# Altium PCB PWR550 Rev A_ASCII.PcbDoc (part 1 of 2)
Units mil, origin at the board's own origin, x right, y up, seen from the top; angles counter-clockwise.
Board outline 5200 x 2850 mil, 4 copper layers (Top Layer, INTERNAL 1, INTERNAL 2, Bottom Layer), stack 60.3 mil thick; 145 components, 78 nets, 363 pads, 156 vias.
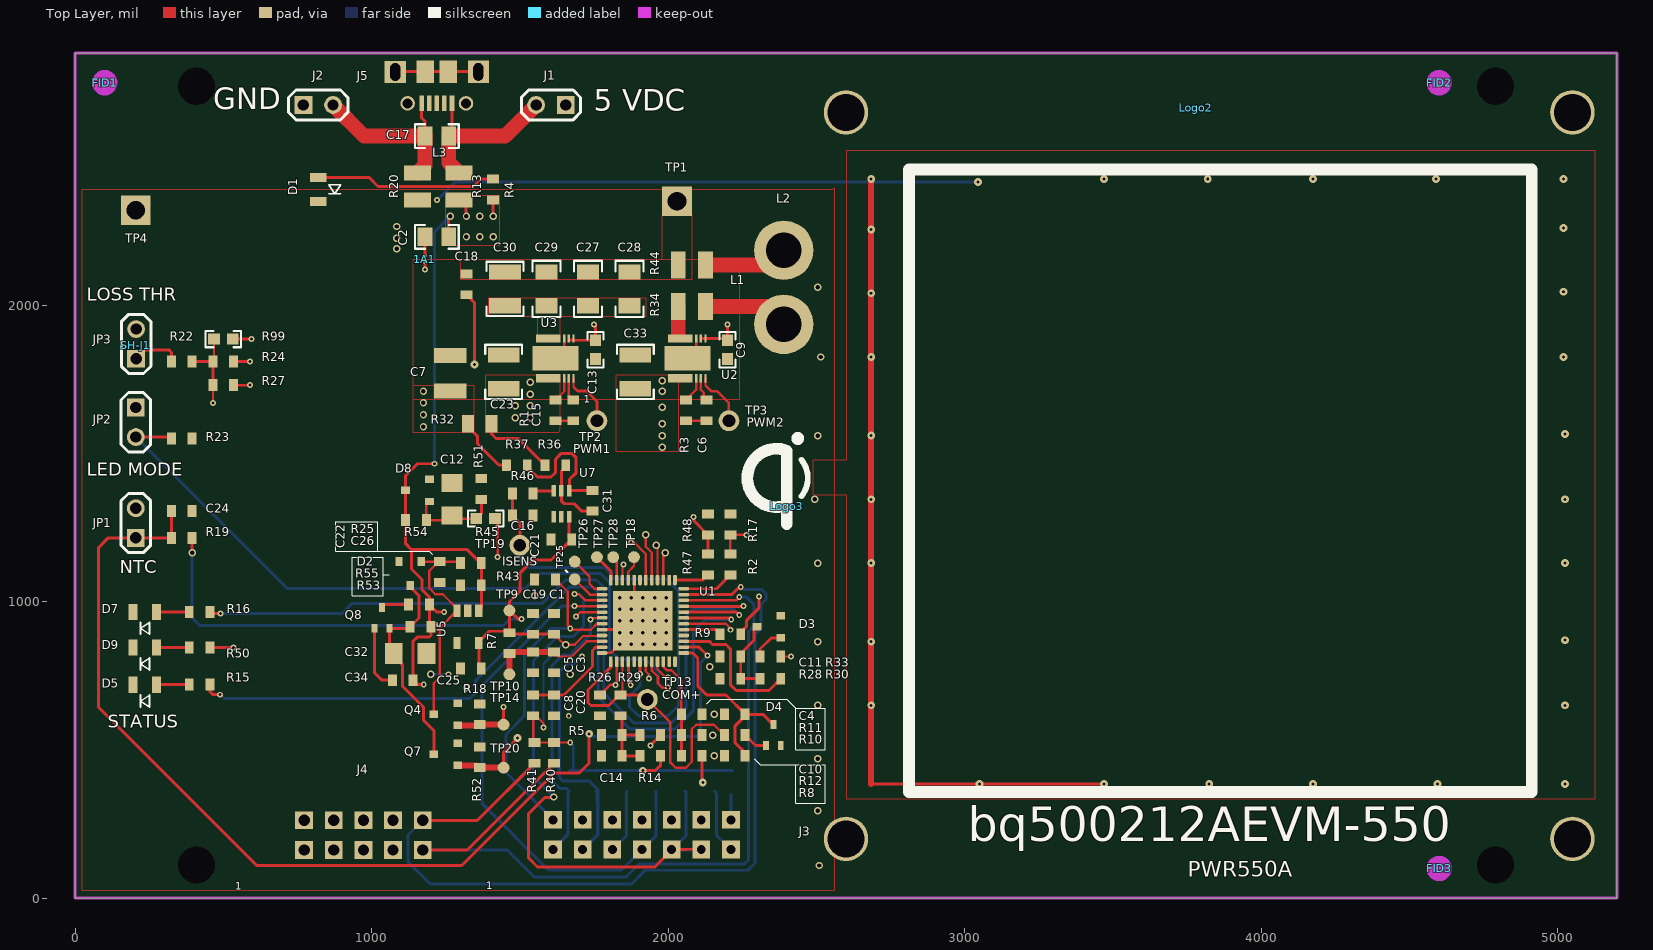
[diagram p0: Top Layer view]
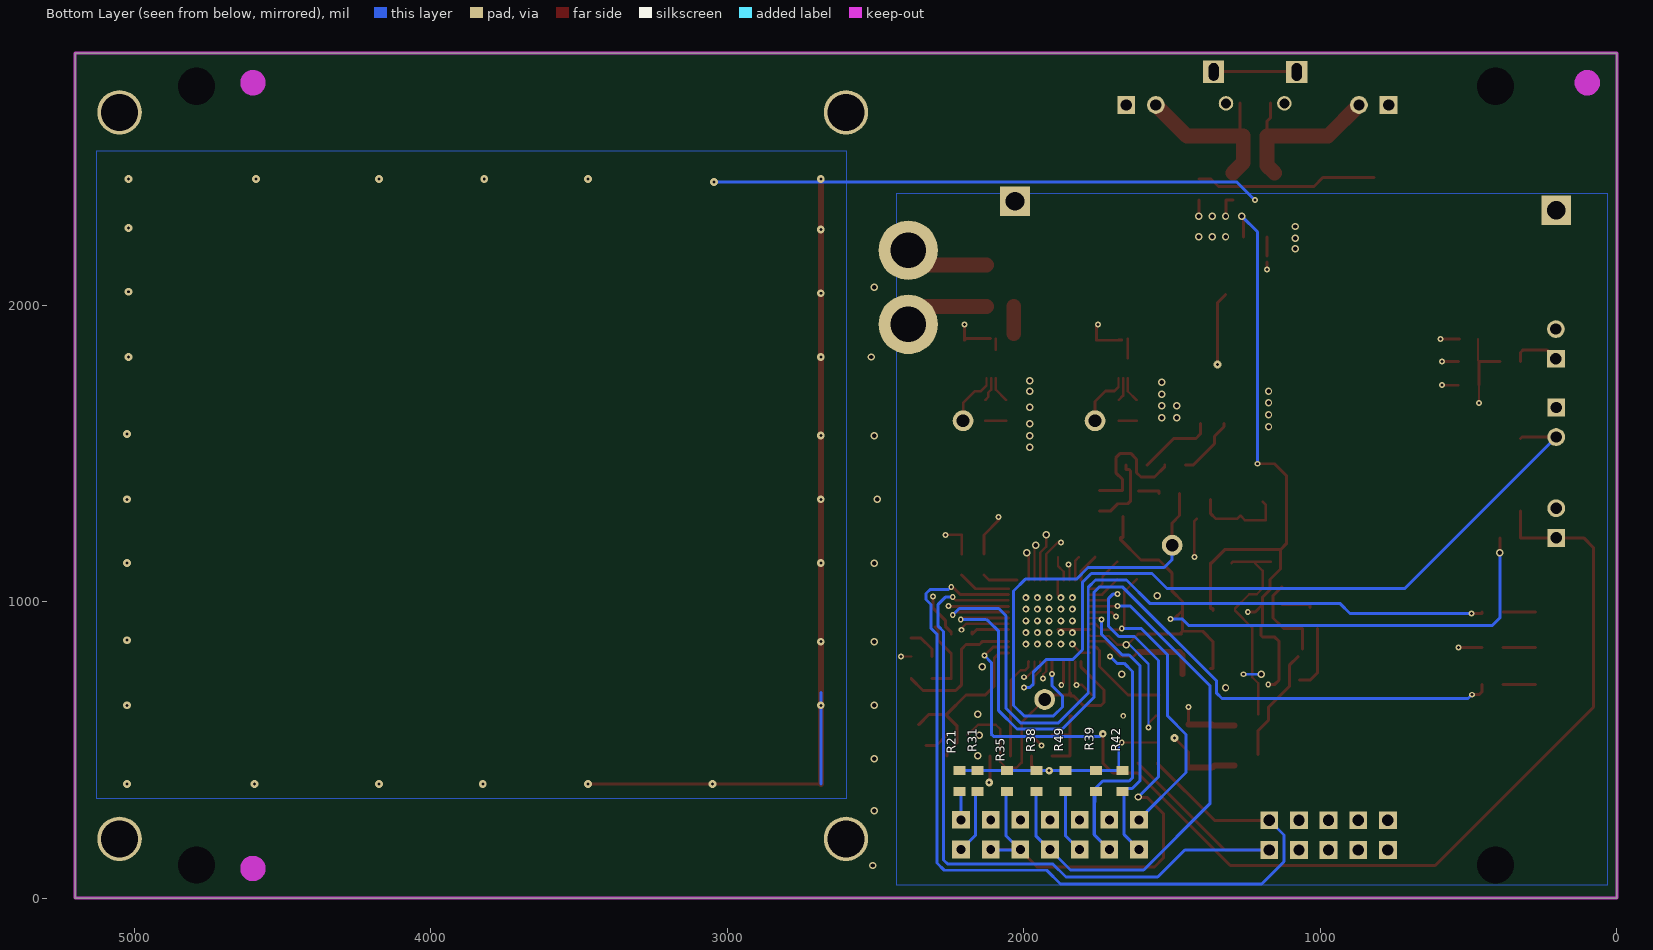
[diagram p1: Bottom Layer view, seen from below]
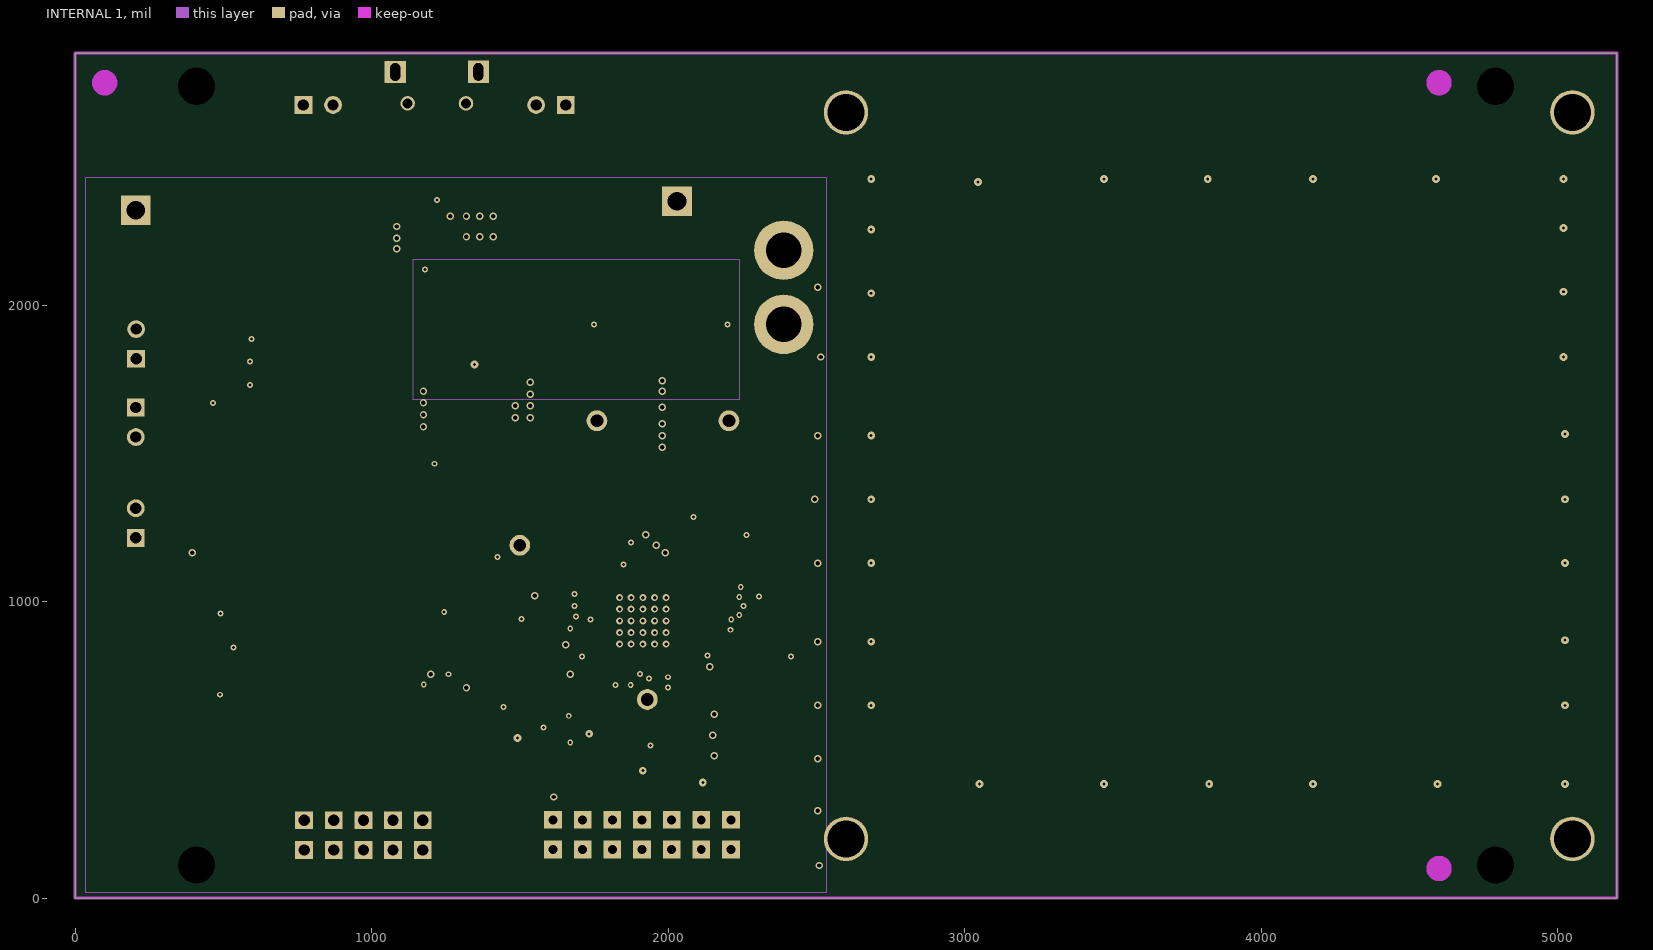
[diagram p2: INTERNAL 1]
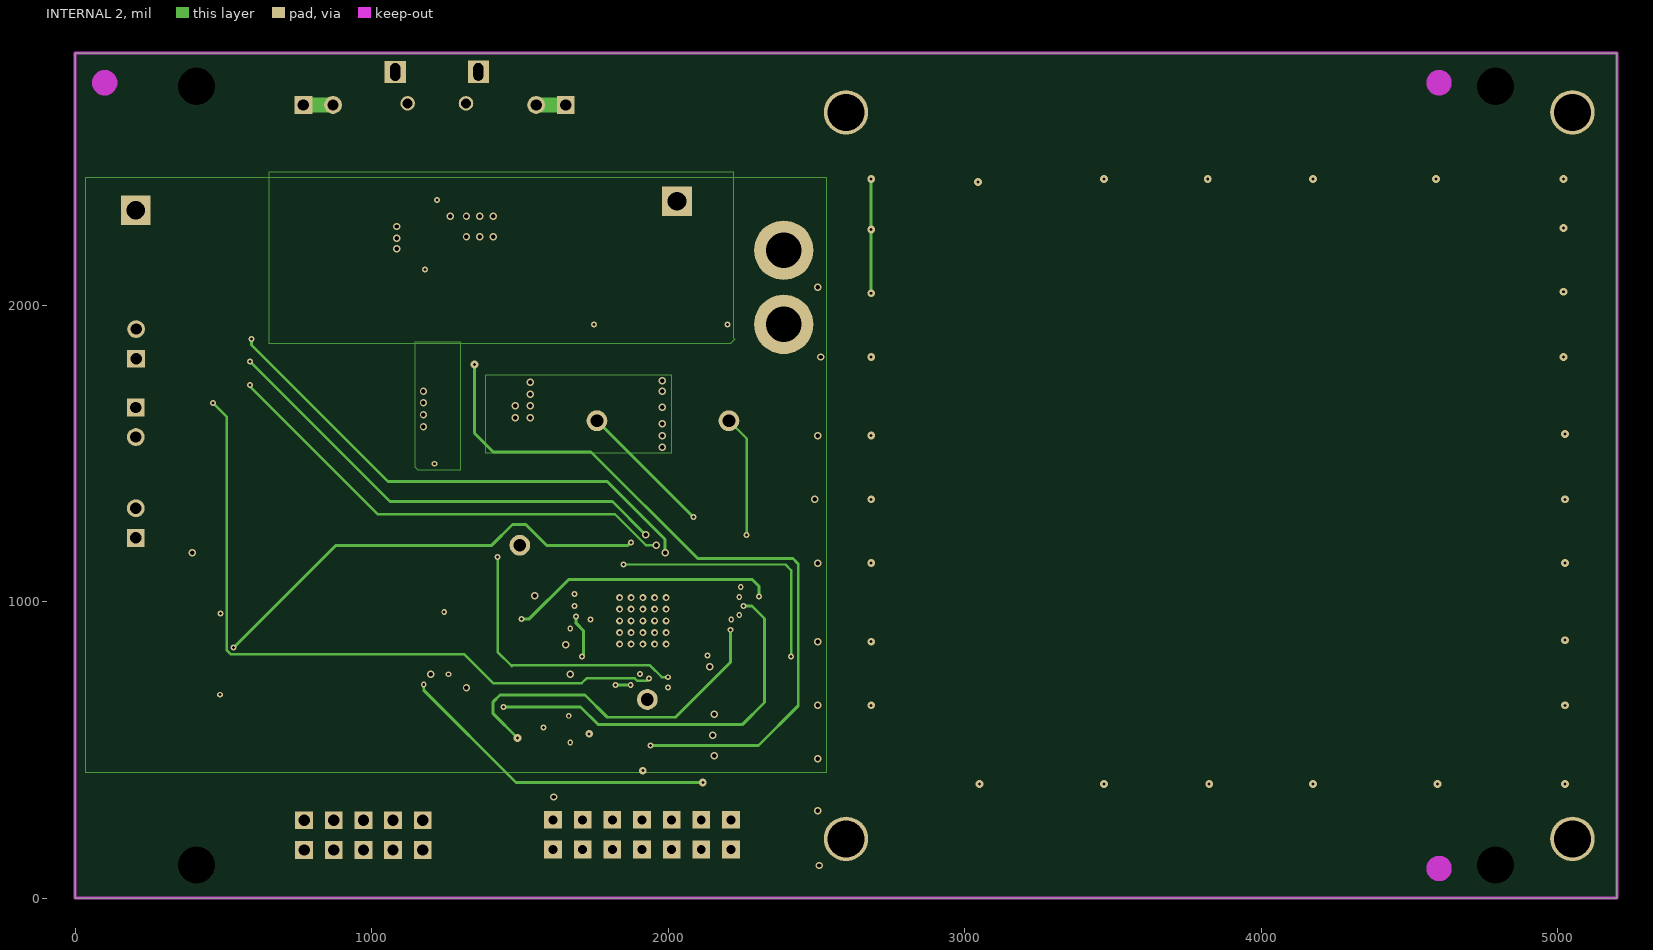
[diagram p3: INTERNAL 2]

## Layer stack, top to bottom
Top Layer: signal copper 2.8
Dielectric: core 18.3, 370HR, Dk 4.8
INTERNAL 1: signal copper 2.8
Dielectric: prepreg 12.5, 370HR, Dk 4.8
INTERNAL 2: signal copper 2.8
Dielectric: core 18.3, 370HR, Dk 4.8
Bottom Layer: signal copper 2.8

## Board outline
0,0 0,2850 5200,2850 5200,0

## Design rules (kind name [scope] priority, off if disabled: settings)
AcuteAngle [All] p0: scope1count=1 scope1_0_kind=Board scope1_0_value=Board scope2count=1 scope2_0_kind=Board scope2_0_value=Board commentlength=0 minimum=4.50000000000000E+0001
AcuteAngle [All] p1: minimum=4.50000000000000E+0001 checktracksonly=FALSE
AssemblyTestPointUsage [All] p0: scope1count=1 scope1_0_kind=Board scope1_0_value=Board scope2count=1 scope2_0_kind=Board scope2_0_value=Board commentlength=0
AssemblyTestPointUsage [All] p1: valid=2
AssemblyTestpoint [All] p0: scope1count=1 scope1_0_kind=Board scope1_0_value=Board scope2count=1 scope2_0_kind=Board scope2_0_value=Board commentlength=0
Clearance [All] p0: scope1count=1 scope1_0_kind=Board scope1_0_value=Board scope2count=1 scope2_0_kind=Board scope2_0_value=Board commentlength=0 gap=7
Clearance Clearance_Poly [All] p0 off: scope1count=1 scope1_0_kind=Board scope1_0_value=Board scope2count=1 scope2_0_kind=Board scope2_0_value=Board commentlength=48 gap=10 // Protel DXP Scope 1 Expression Was: InPolygon
Clearance Clearance_BoardEdge [All] p0 off: scope1count=1 scope1_0_kind=Board scope1_0_value=Board scope2count=1 scope2_0_kind=Board scope2_0_value=Board commentlength=48 gap=25 // Protel DXP Scope 2 Expression Was: IsKeepOut
Clearance Clearance_BoardEdge_Poly [All] p0 off: scope1count=1 scope1_0_kind=Board scope1_0_value=Board scope2count=1 scope2_0_kind=Board scope2_0_value=Board commentlength=48 gap=25 // Protel DXP Scope 2 Expression Was: IsKeepOut
Clearance Clearance_BoardEdge_MountingHoles [All] p0 off: scope1count=1 scope1_0_kind=Board scope1_0_value=Board scope2count=1 scope2_0_kind=Board scope2_0_value=Board commentlength=48 gap=50 // Protel DXP Scope 2 Expression Was: IsKeepOut
Clearance Clearance_BoardEdge_MountingHoles [OnCopper and InComponentClass('Mounting Holes') vs IsKeepOut] p1: gap=50
Clearance Clearance_BoardEdge_Poly [OnCopper and InPoly vs IsKeepOut] p2: gap=25
Clearance Clearance_BoardEdge [OnCopper and Not InComponentClass('Logo') and not InComponentClass('FiducialMark') and not InRegion(1000,500,4000,800) and Not IsKeepout vs IsKeepOut] p3: gap=25
Clearance Clearance_Poly [InPolygon] p4: gap=10
Clearance [All] p5: gap=7
ComponentClearance [All] p0 off: scope1count=1 scope1_0_kind=Board scope1_0_value=Board scope2count=1 scope2_0_kind=Board scope2_0_value=Board commentlength=0 gap=10 collisioncheckmode=3
ComponentClearance ComponentClearance_THtoTH [All] p0 off: scope1count=1 scope1_0_kind=Board scope1_0_value=Board scope2count=1 scope2_0_kind=Board scope2_0_value=Board commentlength=54 gap=100 collisioncheckmode=3 // Protel DXP Scope 2 Expression Was: IsThruComponent
ComponentClearance ComponentClearance_THtoSMT [All] p0 off: scope1count=1 scope1_0_kind=Board scope1_0_value=Board scope2count=1 scope2_0_kind=Board scope2_0_value=Board commentlength=53 gap=20 collisioncheckmode=3 // Protel DXP Scope 2 Expression Was: IsSMTComponent
ComponentClearance ComponentClearance_SmallPassives [All] p0 off: scope1count=1 scope1_0_kind=Board scope1_0_value=Board scope2count=1 scope2_0_kind=Board scope2_0_value=Board commentlength=508 gap=10 collisioncheckmode=3 // Protel DXP Scope 2 Expression Was: HasFootprint('0201*') or HasFootprint('0402*') or HasFootprint('0508') or HasFootprint('0603*') or HasFootprint('0612') or HasFootprint('0805*') or HasFootprint('0815*') or HasFootprint('0830*') or HasFootprint('1206*') or HasFootprint('1210*') or HasFootprint('1808*') or HasFootprint('1812*') or HasFootprint('1825*') or HasFootprint('2010*') or HasFootprint('2220*') or HasFootprint('2225*') or HasFootprint('2512*') or HasFootprint('2728*') or HasFootprint('3518*')
ComponentClearance ComponentClearance_MountingHoles [All] p0 off: scope1count=1 scope1_0_kind=ComponentClass scope1_0_value="Mounting Holes" scope2count=1 scope2_0_kind=Board scope2_0_value=Board commentlength=0 gap=25 collisioncheckmode=3
ComponentClearance ComponentClearance_ScrewToNut [All] p0 off: scope1count=1 scope1_0_kind=Board scope1_0_value=Board scope2count=1 scope2_0_kind=Board scope2_0_value=Board commentlength=71 gap=10 collisioncheckmode=3 // Protel DXP Scope 2 Expression Was: (HasFootprint('Keystone_1902C'))
ComponentClearance ComponentClearance_Logo [All] p0 off: scope1count=1 scope1_0_kind=ComponentClass scope1_0_value=Logo scope2count=1 scope2_0_kind=Board scope2_0_value=Board commentlength=0 gap=5 collisioncheckmode=3
ComponentClearance ComponentClearance_Logo [InComponentClass(Logo)] p1 off: gap=5 collisioncheckmode=3 verticalgap=5 showdistances=FALSE
ComponentClearance ComponentClearance_ScrewToNut [(HasFootprint('NY PMS 440 0025 PH')) vs (HasFootprint('Keystone_1902C'))] p2 off: gap=10 collisioncheckmode=3 verticalgap=10 showdistances=FALSE
ComponentClearance ComponentClearance_MountingHoles [InComponentClass('Mounting Holes')] p3 off: gap=25 collisioncheckmode=3 verticalgap=100000 showdistances=FALSE
ComponentClearance ComponentClearance_SmallPassives [HasFootprint('0201*') or HasFootprint('0402*') or HasFootprint('0508') or HasFootprint('0603*') or HasFootprint('0612') or HasFootprint('0805*') or HasFootprint('0815*') or HasFootprint('0830*') or HasFootprint('1206*') or HasFootprint('1210*') or HasFootprint('1808*') or HasFootprint('1812*') or HasFootprint('1825*') or HasFootprint('2010*') or HasFootprint('2220*') or HasFootprint('2225*') or HasFootprint('2512*') or HasFootprint('2728*') or HasFootprint('3518*') vs HasFootprint('0201*') or HasFootprint('0402*') or HasFootprint('0508') or HasFootprint('0603*') or HasFootprint('0612') or HasFootprint('0805*') or HasFootprint('0815*') or HasFootprint('0830*') or HasFootprint('1206*') or HasFootprint('1210*') or HasFootprint('1808*') or HasFootprint('1812*') or HasFootprint('1825*') or HasFootprint('2010*') or HasFootprint('2220*') or HasFootprint('2225*') or HasFootprint('2512*') or HasFootprint('2728*') or HasFootprint('3518*')] p4 off: gap=10 collisioncheckmode=3 verticalgap=10 showdistances=FALSE
ComponentClearance ComponentClearance_THtoSMT [IsThruComponent vs IsSMTComponent] p5 off: gap=20 collisioncheckmode=3 verticalgap=100000 showdistances=FALSE
ComponentClearance ComponentClearance_THtoTH [IsThruComponent vs IsThruComponent] p6 off: gap=100 collisioncheckmode=3 verticalgap=100000 showdistances=FALSE
ComponentClearance [All] p7 off: gap=10 collisioncheckmode=3 verticalgap=10 showdistances=FALSE
DiffPairsRouting [All] p0: scope1count=1 scope1_0_kind=Board scope1_0_value=Board scope2count=1 scope2_0_kind=Board scope2_0_value=Board commentlength=0
DiffPairsRouting [All] p1: maxlimit=100 minlimit=10 mostfreqgap=10 maxuncoupledlength=1000
FabricationTestPointUsage TestPointUsage [All] p0: scope1count=1 scope1_0_kind=Board scope1_0_value=Board scope2count=1 scope2_0_kind=Board scope2_0_value=Board commentlength=0 valid=2 allowmultiple=FALSE
FabricationTestPointUsage TestPointUsage [All] p1: valid=2 allowmultiple=FALSE
FabricationTestpoint Testpoint [All] p0: scope1count=1 scope1_0_kind=Board scope1_0_value=Board scope2count=1 scope2_0_kind=Board scope2_0_value=Board commentlength=0 side=3 testpointundercomponent=TRUE minsize=40 maxsize=100 preferedsize=60 minholesize=0 maxholesize=40 preferedholesize=32 testpointgrid=1
FabricationTestpoint Testpoint [All] p1: side=3 testpointundercomponent=TRUE minsize=40 maxsize=100 preferedsize=60 minholesize=0 maxholesize=40 preferedholesize=32 testpointgrid=1 allowsidetop=TRUE allowsidebottom=TRUE usegrid=TRUE gridtolerance=0.01
FanoutControl Fanout_Small [All] p0 off: scope1count=1 scope1_0_kind=Board scope1_0_value=Board scope2count=1 scope2_0_kind=Board scope2_0_value=Board commentlength=84 // Protel DXP Scope 1 Expression Was: (CompPinCount < 5)   Fanout_Small (Default Rule)
FanoutControl Fanout_Default [All] p0: scope1count=1 scope1_0_kind=Board scope1_0_value=Board scope2count=1 scope2_0_kind=Board scope2_0_value=Board commentlength=30 // Fanout_Default (Default Rule)
FanoutControl Fanout_SOIC [All] p0 off: scope1count=1 scope1_0_kind=Board scope1_0_value=Board scope2count=1 scope2_0_kind=Board scope2_0_value=Board commentlength=71 // Protel DXP Scope 1 Expression Was: IsSOIC   Fanout_SOIC (Default Rule)
FanoutControl Fanout_BGA [All] p0 off: scope1count=1 scope1_0_kind=Board scope1_0_value=Board scope2count=1 scope2_0_kind=Board scope2_0_value=Board commentlength=69 // Protel DXP Scope 1 Expression Was: IsBGA   Fanout_BGA (Default Rule)
FanoutControl Fanout_LCC [All] p0 off: scope1count=1 scope1_0_kind=Board scope1_0_value=Board scope2count=1 scope2_0_kind=Board scope2_0_value=Board commentlength=69 // Protel DXP Scope 1 Expression Was: IsLCC   Fanout_LCC (Default Rule)
FanoutControl Fanout_LCC [IsLCC] p1: bgadir=Out bgaviamode=Centered fanoutstyle=Auto fanoutdirection=Alternating viagrid=1 // Fanout_LCC (Default Rule)
FanoutControl Fanout_BGA [IsBGA] p2: bgadir=Out bgaviamode=Centered fanoutstyle=Auto fanoutdirection=Alternating viagrid=1 // Fanout_BGA (Default Rule)
FanoutControl Fanout_Default [All] p4: bgadir=Out bgaviamode=Centered fanoutstyle=Auto fanoutdirection=Alternating viagrid=1 // Fanout_Default (Default Rule)
FanoutControl Fanout_Small [(CompPinCount < 5)] p5: bgadir=Out bgaviamode=Centered fanoutstyle=Auto fanoutdirection=OutThenIn viagrid=1 // Fanout_Small (Default Rule)
Height [All] p0: scope1count=1 scope1_0_kind=Board scope1_0_value=Board scope2count=1 scope2_0_kind=Board scope2_0_value=Board commentlength=0
HoleSize [All] p0: scope1count=1 scope1_0_kind=Board scope1_0_value=Board scope2count=1 scope2_0_kind=Board scope2_0_value=Board commentlength=0 absolutevalues=TRUE maxlimit=251 minlimit=6 maxpercent=80.000 minpercent=20.000
HoleSize [All] p1: absolutevalues=TRUE maxlimit=251 minlimit=6 maxpercent=80.000 minpercent=20.000
HoleToHoleClearance [All] p0: scope1count=1 scope1_0_kind=Board scope1_0_value=Board scope2count=1 scope2_0_kind=Board scope2_0_value=Board commentlength=0
LayerPairs [All] p0: scope1count=1 scope1_0_kind=Board scope1_0_value=Board scope2count=1 scope2_0_kind=Board scope2_0_value=Board commentlength=0 enforce=TRUE
MinimumAnnularRing [All] p0 off: scope1count=1 scope1_0_kind=Board scope1_0_value=Board scope2count=1 scope2_0_kind=Board scope2_0_value=Board commentlength=0 minimumring=8
MinimumAnnularRing [All] p1 off: minimumring=8
MinimumSolderMaskSliver MinimumSolderMaskSliver_1 [All] p0: scope1count=1 scope1_0_kind=Board scope1_0_value=Board scope2count=1 scope2_0_kind=Board scope2_0_value=Board commentlength=0
MinimumSolderMaskSliver MinimumSolderMaskSliver_U1 [All] p0: scope1count=1 scope1_0_kind=Footprint scope1_0_value=QFN48[RGZ] scope2count=1 scope2_0_kind=Board scope2_0_value=Board commentlength=0
MinimumSolderMaskSliver MinimumSolderMaskSliver_Logo [All] p0: scope1count=1 scope1_0_kind=ComponentClass scope1_0_value=Logo scope2count=1 scope2_0_kind=ComponentClass scope2_0_value=Logo commentlength=0
MinimumSolderMaskSliver MinimumSolderMaskSliver_U1 [HasFootprint('QFN48[RGZ]')] p1: minsoldermaskwidth=3.7
MinimumSolderMaskSliver MinimumSolderMaskSliver_1 [All] p2: minsoldermaskwidth=5
MinimumSolderMaskSliver MinimumSolderMaskSliver_Logo [InComponentClass('Logo') vs InComponentClass('Logo')] p3: minsoldermaskwidth=0.7
NetAntennae [All] p0: scope1count=1 scope1_0_kind=Board scope1_0_value=Board scope2count=1 scope2_0_kind=Board scope2_0_value=Board commentlength=0
PasteMaskExpansion [All] p0: scope1count=1 scope1_0_kind=Board scope1_0_value=Board scope2count=1 scope2_0_kind=Board scope2_0_value=Board commentlength=0 expansion=0
PlaneClearance [All] p0: scope1count=1 scope1_0_kind=Board scope1_0_value=Board scope2count=1 scope2_0_kind=Board scope2_0_value=Board commentlength=0 clearance=20
PlaneConnect [All] p0: scope1count=1 scope1_0_kind=Board scope1_0_value=Board scope2count=1 scope2_0_kind=Board scope2_0_value=Board commentlength=0 planeconnectstyle=Relief reliefexpansion=10 reliefentries=4 reliefconductorwidth=10 reliefairgap=10
PlaneConnect [All] p1: planeconnectstyle=Relief reliefexpansion=10 reliefentries=4 reliefconductorwidth=10 reliefairgap=10
PolygonConnect [All] p0: scope1count=1 scope1_0_kind=Board scope1_0_value=Board scope2count=1 scope2_0_kind=Board scope2_0_value=Board commentlength=0 connectstyle=Direct reliefconductorwidth=10 reliefentries=4 polygonreliefangle="90 Angle"
PolygonConnect [All] p1: connectstyle=Direct reliefconductorwidth=10 reliefentries=4 polygonreliefangle="90 Angle" airgapwidth=10
RoutingCorners [All] p0: scope1count=1 scope1_0_kind=Board scope1_0_value=Board scope2count=1 scope2_0_kind=Board scope2_0_value=Board commentlength=0 cornerstyle=45-Degree minsetback=10 maxsetback=10
RoutingCorners [All] p1: cornerstyle=45-Degree minsetback=10 maxsetback=10
RoutingLayers [All] p0: scope1count=1 scope1_0_kind=Board scope1_0_value=Board scope2count=1 scope2_0_kind=Board scope2_0_value=Board commentlength=0 top layer=Automatic mid layer 1=Automatic mid layer 2=Automatic bottom layer=Automatic
RoutingPriority [All] p0: scope1count=1 scope1_0_kind=Board scope1_0_value=Board scope2count=1 scope2_0_kind=Board scope2_0_value=Board commentlength=0
RoutingTopology [All] p0: scope1count=1 scope1_0_kind=Board scope1_0_value=Board scope2count=1 scope2_0_kind=Board scope2_0_value=Board commentlength=0 topology=Shortest
RoutingVias [All] p0: scope1count=1 scope1_0_kind=Board scope1_0_value=Board scope2count=1 scope2_0_kind=Board scope2_0_value=Board commentlength=0 holewidth=12 width=26 viastyle="Through Hole" minholewidth=10 minwidth=20 maxholewidth=20 maxwidth=40
RoutingVias [All] p1: holewidth=12 width=26 viastyle="Through Hole" minholewidth=10 minwidth=20 maxholewidth=20 maxwidth=40
SMDNeckDown [All] p0 off: scope1count=1 scope1_0_kind=Board scope1_0_value=Board scope2count=1 scope2_0_kind=Board scope2_0_value=Board commentlength=0 percent=40.000
SMDNeckDown [All] p1 off: percent=40.000
SMDToCorner [All] p0: scope1count=1 scope1_0_kind=Board scope1_0_value=Board scope2count=1 scope2_0_kind=Board scope2_0_value=Board commentlength=0 distance=30000
SMDToCorner [All] p1: distance=30000
ShortCircuit [All] p0: scope1count=1 scope1_0_kind=Net scope1_0_value=AGND scope2count=1 scope2_0_kind=Net scope2_0_value=GND commentlength=0 allowed=TRUE
ShortCircuit [InNet('AGND') vs InNet('GND')] p1: allowed=TRUE
SilkToSilkClearance [All] p0: scope1count=1 scope1_0_kind=Board scope1_0_value=Board scope2count=1 scope2_0_kind=Board scope2_0_value=Board commentlength=0
SilkToSilkClearance [All] p1: silktosilkclearance=0
SilkscreenOverComponentPads [All] p0: scope1count=1 scope1_0_kind=Board scope1_0_value=Board scope2count=1 scope2_0_kind=Board scope2_0_value=Board commentlength=0
SilkscreenOverComponentPads [All] p1: minsilkscreentomaskgap=5
SolderMaskExpansion [All] p0: scope1count=1 scope1_0_kind=Board scope1_0_value=Board scope2count=1 scope2_0_kind=Board scope2_0_value=Board commentlength=0 expansion=1
SolderMaskExpansion [All] p1: expansion=1
UnRoutedNet [All] p0: scope1count=1 scope1_0_kind=Board scope1_0_value=Board scope2count=1 scope2_0_kind=Board scope2_0_value=Board commentlength=0
Width [All] p0: scope1count=1 scope1_0_kind=Board scope1_0_value=Board scope2count=1 scope2_0_kind=Board scope2_0_value=Board commentlength=0 maxlimit=100 minlimit=6 preferedwidth=10
Width [All] p1: maxlimit=100 minlimit=6 preferedwidth=10 checkconnectedcopper=TRUE
12 further rules are at their usual default settings.

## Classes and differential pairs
component class Shunt: SH-J1
component class Hardware: !PCB FID1 FID2 FID3 Logo2 Logo3 SH-J1 ZZ1 ZZ2 ZZ3 ZZ4 ZZ5 ZZ6 ZZ7 ZZ8 ZZ9 ZZ10
component class FiducialMark: FID1 FID2 FID3
component class AssemblyNote: ZZ1 ZZ2 ZZ3 ZZ4 ZZ5 ZZ6 ZZ7 ZZ8 ZZ9 ZZ10
component class "SHEET 3": J3 J4 R21 R31 R35 R38 R39 R42 R49
component class "SHEET 2": C1 C3 C4 C5 C8 C10 C11 C19 C20 C24 D3 D4 D5 D7 D9 JP1 JP2 JP3 R2 R7 R8 R9 R10 R11 R12 R15 R16 R17 R19 R22 R23 R24 R27 R28 R30 R33 R40 R41 R43 R47 R48 R50 R99 TP10 TP18 TP25 TP26 TP27 TP28 U1
component class "SHEET 1": 1A1 C2 C6 C7 C9 C12 C13 C14 C15 C16 C17 C18 C21 C22 C23 C25 C26 C27 C28 C29 C30 C31 C32 C33 C34 D1 D2 D8 J1 J2 J5 L1 L2 L3 Q4 Q7 Q8 R1 R3 R4 R5 R6 R14 R18 R25 R26 R29 R32 R36 R37 R45 R46 R51 R52 R53 R54 R55 TP1 TP2 TP3 TP4 TP9 TP13 TP14 TP19 TP20 U2 U3 U5 U7
component class Logo: Logo2

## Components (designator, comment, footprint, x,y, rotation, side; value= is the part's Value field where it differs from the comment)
1A1 "Net-Tie" Net-Tie_10mil 1180,2155 r90 top net-tie
C1 "C0603" C603 1615,925 r270 top
C2 "0805ZD475KAT2A" 0805_HV 1220,2230 r180 top
C3 "C0603" C603 1615,795 r90 top
C4 "C0603" C603 2080,620 r0 top
C5 "C0603" C603 1545,795 r270 top
C6 "C0603" C603 2130,1645 r270 top
C7 "C1210" C1210 1265,1770 r90 top
C8 "C0603" C603 1545,650 r90 top
C9 "C0603C105K4PACTU" 0603 2200,1850 r270 top
C10 "C0603" C603 2225,620 r0 top
C11 "C0603" C603 2210,815 r180 top
C12 "C1206" C1206 1271,1345 r270 top
C13 "C0603C105K4PACTU" 0603 1755,1850 r270 top
C14 "C0603" C603 1810,480 r0 top
C15 "C0603" C603 1680,1645 r90 top
C16 "C0603" C603 1510,1290 r180 top
C17 "0805ZD475KAT2A" 0805_HV 1220,2570 r180 top
C18 "C0603" C603 1320,2070 r90 top
C19 "C0603" C603 1545,925 r90 top
C20 "C0603" C603 1615,650 r270 top
C21 "C0603" C603 1640,1210 r0 top
C22 "C0603" C603 1230,1100 r90 top
C23 "C1210C106K8PACTU" 1210 1445,1775 r90 top
C24 "C0603" C603 360,1305 r0 top
C25 "C0603" C603 1335,775 r0 top
C26 "C0603" C603 1335,1055 r0 top
C27 "C3216X7R2A104K" 1206 1730,2055 r90 top
C28 "C3216X7R2A104K" 1206 1870,2055 r90 top
C29 "C3216X7R2A104K" 1206 1590,2055 r90 top
C30 "C3225C0G1H104K250AA" 1210 1450,2055 r90 top
C31 "C0603" C603 1745,1340 r90 top
C32 "C1206" C1206 1130,825 r0 top
C33 "C1210C106K8PACTU" 1210 1890,1775 r90 top
C34 "C0603" C603 1105,735 r0 top
D1 "D-LED_0805" LED-0805 820,2390 r90 top
D2 "D-BAT54" SOT-23 1130,1095 r90 top
D3 "D-BAT54" SOT-23 2340,915 r0 top
D4 "D-BAT54SWT1G" SOT-323#1 2355,550 r0 top
D5 "D-LED_0805" LED-0805 235,720 r0 top
D7 "D-LED_0805" LED-0805 235,965 r0 top
D8 "D-BAT54" SOT-23 1155,1375 r0 top
D9 "D-LED_0805" LED-0805 235,845 r0 top
FID1 "Fiducial" Fiducial10-20 100,2750 r0 top
FID2 "Fiducial" Fiducial10-20 4600,2750 r0 top
FID3 "Fiducial" Fiducial10-20 4600,100 r0 top
J1 "HEADER_1X2" HDR100_1X2 1655,2675 r180 top
J2 "HEADER_1X2" HDR100_1X2 770,2675 r0 top
J3 "HEADER_14PJTAG" HEADER_2500_ 1612,164 r0 top
J4 "CONN_2510-6002UB" CONN_2510-6002UB 772.5,162.5 r0 top
J5 "CONN_MICRO-USB-B" CONN_MICRO-USB-B 1220,2769 r180 top
JP1 "JUMPER_2X100MIL" HDR100_1X2 205,1215 r90 top
JP2 "JUMPER_2X100MIL" HDR100_1X2 205,1655 r270 top
JP3 "JUMPER_2X100MIL" HDR100_1X2 206,1819 r90 top
L1 "IND_DLW5BSN_SERIES" DLW5BSN_SERIES 2080,2065 r180 top
L2 "IND_TXL05001" IND_TXL05001 3890,2060 r0 top locked
L3 "IND_DLW5BSN_SERIES" DLW5BSN_SERIES 1225,2400 r270 top
Logo2 "Texas Instruments" TI_Horizontal_Overlay_Medium 3780,2665 r0 top
Logo3 "Silk" "QI Logo" 2400,1322 r0 top
Q4 "BSS138" SOT-23 1250,620 r0 top
Q7 "BSS138" SOT-23 1250,485 r0 top
Q8 "DTC114EUAT106" SOT-323#2 1035,945 r0 top
R1 "R0603_1%" R603 1620,1645 r270 top
R2 "R0603_1%" R603 2210,1125 r270 top
R3 "R0603_1%" R603 2060,1645 r90 top
R4 "R0603" R0603 1410,2390 r270 top
R5 "R0603_1%" R603 1810,550 r0 top
R6 "R0603_1%" R603 1940,550 r0 top
R7 "R0805_1%" R603 1465,860 r270 top
R8 "R0603_1%" R603 2225,480 r0 top
R9 "R0603_1%" R603 2210,890 r0 top
R10 "R0603_1%" R603 2080,480 r0 top
R11 "R0603_1%" R603 2080,550 r180 top
R12 "R0603_1%" R603 2225,550 r0 top
R14 "R0603_1%" R603 1940,480 r0 top
R15 "R0603_1%" R603 420,720 r180 top
R16 "R0603_1%" R603 420,965 r180 top
R17 "R0603_1%" R603 2210,1260 r270 top
R18 "R0603_1%" R603 1365,620 r270 top
R19 "R0603_1%" R603 360,1215 r0 top
R21 "R0603_1%" R603 2217,395 r270 bottom
R22 "R0603_1%" R603 360,1810 r0 top
R23 "R0603_1%" R603 360,1550 r180 top
R24 "R0603_1%" R603 500,1810 r0 top
R25 "R0603_1%" R603 1335,1130 r0 top
R26 "R0603_1%" R603 1770,650 r270 top
R27 "R0603_1%" R603 500,1730 r0 top
R28 "R0603_1%" R603 2210,740 r0 top
R29 "R0603_1%" R603 1840,650 r90 top
R30 "R0603_1%" R603 2345,740 r0 top
R31 "R0603_1%" R603 2157,395 r270 bottom
R32 "R0805" R0805 1365,1600 r180 top
R33 "R0603_1%" R603 2345,815 r0 top
R35 "R0603_1%" R603 2057,395 r270 bottom
R36 "R0603_1%" R603 1620,1460 r0 top
R37 "R0603_1%" R603 1490,1460 r0 top
R38 "R0603_1%" R603 1957,395 r270 bottom
R39 "R0603_1%" R603 1757,395 r270 bottom
R40 "R0603_1%" R603 1615,490 r270 top
R41 "R0603_1%" R603 1550,490 r270 top
R42 "R0603_1%" R603 1667,395 r270 bottom
R43 "R0603_1%" R603 1585,1075 r0 top
R45 "CRCW06031M00JNEA" 0603 1385,1280 r180 top
R46 "R0603_1%" R603 1510,1365 r0 top
R47 "R0603_1%" R603 2135,1125 r270 top
R48 "R0603_1%" R603 2135,1260 r270 top
R49 "R0603_1%" R603 1860,395 r270 bottom
R50 "R0603_1%" R603 420,845 r180 top
R51 "R0603_1%" R603 1370,1380 r270 top
R52 "R0603_1%" R603 1365,475 r270 top
R53 "R0603_1%" R603 1165,915 r0 top
R54 "R0603_1%" R603 1150,1275 r180 top
R55 "R0603_1%" R603 1160,990 r0 top
R99 "RC0603FR-0786K6L" 0603 500,1885 r0 top
SH-J1 "SNT-100-BK-G" SNT-100-BK-G 205,1865 r90 top
TP1 "TP-5012-WHITE" TH-63 2030,2350 r0 top
TP2 "TP_1045" TP_1045 1760,1610 r90 top
TP3 "TP_1045" TP_1045 2205,1610 r90 top
TP4 "TP-5011-BLACK" TH-63 205,2320 r0 top
TP9 "TP_40_SMT" TP_40_SMT 1465,970 r0 top
TP10 "TP_40_SMT" TP_40_SMT 1465,755 r180 top
TP13 "TP_1045" TP_1045 1930,670 r270 top
TP14 "TP_40_SMT" TP_40_SMT 1445,585 r0 top
TP18 "TP_40_SMT" TP_40_SMT 1885,1150 r0 top
TP19 "TP_1045" TP_1045 1500,1190 r90 top
TP20 "TP_40_SMT" TP_40_SMT 1445,440 r0 top
TP25 "TP_40_SMT" TP_40_SMT 1685,1075 r0 top
TP26 "TP_40_SMT" TP_40_SMT 1685,1135 r0 top
TP27 "TP_40_SMT" TP_40_SMT 1760,1150 r90 top
TP28 "TP_40_SMT" TP_40_SMT 1815,1150 r90 top
U1 "BQ500210RGZ" QFN48[RGZ] 1915,935 r180 top
U2 "CSD97374CQ4M" QFN4.5X3.5MM_8PWD 2065,1820 r180 top
U3 "CSD97374CQ4M" QFN4.5X3.5MM_8PWD 1620,1820 r180 top
U5 "TLV70033DDC" DBV-5 1325,915 r270 top
U7 "INA21XDCK" DCK-6 1640,1330 r0 top
ZZ1 "This Assembly Note is for PCB labels only" AssemblyNoteLabel -200,7900 r0 top
ZZ2 "These assemblies are ESD sensitive, ESD precautions shall be observed." AssemblyNote -200,7800 r90 top
ZZ3 "These assemblies must be clean and free from flux and all contaminants. Use of no clean flux is not acceptable." AssemblyNote -200,7700 r0 top
ZZ4 "These assemblies must comply with workmanship standards IPC-A-610 Class 2., unless otherwise specified." AssemblyNote -200,7600 r0 top
ZZ5 "Wurth Elektronik (P/N 760-308-111)   www.we-online.de (Oliver Opitz, Oliver.Opitz@we-online.de)" AssemblyNote -200,7500 r0 top
ZZ6 "If part number GP1500-0.020-00-0404 is used the Sil-Pads need to be cut into 2 inch squares." AssemblyNote -200,7400 r0 top
ZZ7 "Solder Coil leads to plated through holes near TP1 and TP2" AssemblyNote -200,7300 r0 top
ZZ8 "Apply thin layer of SA-1000 between Aluminum Plate MCH003 and PCB during installation" AssemblyNote -200,7200 r0 top
ZZ9 "See PWR045 Assembly Guide for build up on L2 and assoicated hardware" AssemblyNote -200,7100 r0 top
ZZ10 "Label will have the following:  CE Mark (min 5 mm, in proper proportion)  This ISM device complies with Part 18 of the FCC Rule.This ISM device complies with Canadian ICES-001. Cet appareil ISM est conforme à la norme NMB-001 du Canada." AssemblyNote -200,7000 r0 top

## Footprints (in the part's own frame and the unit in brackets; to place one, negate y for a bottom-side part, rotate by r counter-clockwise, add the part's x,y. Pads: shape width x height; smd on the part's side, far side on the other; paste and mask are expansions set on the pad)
0603 [mm] "0603 from SM-752 data"
  rect 1x0.95 smd: 1(-0.8,0) 2(0.8,0)
  silkscreen extent -1.52,-0.69 1.52,0.69
0805_HV [mil] "0805 with 30mil clearance between pads"
  rect 50x63 smd: 1(-40,0) 2(40,0)
  silkscreen extent -74,-40 74,40
1206 [mm] "1206 from SM-752 data"
  rect 1.3x1.85 smd: 1(-1.45,0) 2(1.45,0)
  silkscreen extent -2.4,-1.21 2.4,1.21
1210 [mm] "1210 from SM-752 data"
  rect 1.3x2.7 smd: 1(-1.45,0) 2(1.45,0)
  silkscreen extent -2.32,-1.57 2.32,1.57
AssemblyNote [mil] "Assembly Note"
AssemblyNoteLabel [mil] "Assembly Note for PCB Labels"
C603 [mil]
  rect 30x40 smd mask+2: 1(-35,0) 2(35,0)
C1206 [mil]
  rect 60x70 smd: 1(-55,0) 2(55,0)
C1210 [mil]
  rect 50x110 smd mask+2: 1(60,0) 2(-60,0)
CONN_2510-6002UB [mil]
  rect 60x60 hole 38: 1(0,0) 2(0,100) 3(100,0) 4(100,100) 5(200,0) 6(200,100) 7(300,0) 8(300,100) 9(400,0) 10(400,100)
CONN_MICRO-USB-B [mm]
  rect 0.4x1.35 smd mask+0.03: 1(-1.3,2.25) 2(-0.65,2.25) 3(0,2.25) 4(0.65,2.25) 5(1.3,2.25)
  rect 1.8x1.9 hole 0.85 slot 1.5 at 90 deg: 6(-3.56,-0.45) 9(3.56,-0.44)
  rect 1.5x1.9 smd: 7(-0.99,-0.45) 8(1,-0.45)
  round 1.25 hole 0.85 unplated: 10(2.5,2.25) 11(-2.5,2.25)
DBV-5 [mil]
  rect 42x25 smd: 1(-54.5,37) 2(-54.5,0) 3(-54.5,-37) 4(54.5,-37) 5(54.5,37)
DCK-6 [mil]
  rect 15x38 smd: 1(-25.9,-43.4) 2(0.1,-43.4) 3(26.1,-43.4) 4(26.1,43.6) 5(0.1,43.6) 6(-25.9,43.6)
DLW5BSN_SERIES [mil]
  rect 50x90 smd: 1(-46,70) 2(46,70) 3(46,-70) 4(-46,-70)
Fiducial10-20 [mm]
  round 1 smd paste-0.5 mask+0.5: 1(0,0)
  Keep-Out Layer circle w1.178: c0,0 r0.5
HDR100_1X2 [mil]
  rect 60x60 hole 38: 1(0,0)
  round 60 hole 38: 2(100,0)
  silkscreen extent -50,-50 150,50
HEADER_2500_ [mil]
  rect 60x60 hole 30: 1(0,0) 2(0,100) 3(100,0) 4(100,100) 5(200,0) 6(200,100) 7(300,0) 8(300,100) 9(400,0) 10(400,100) 11(500,0) 12(500,100) 13(600,0) 14(600,100)
IND_TXL05001 [mil]
  round 200 hole 120: 1(-1500,125) 2(-1500,-125)
LED-0805 [mil]
  rect 30x55 smd: 1(-40,0) 2(40,0)
  silkscreen extent -14,-75 16,-35
Net-Tie_10mil [mil] "10mil net tie, no solder mask opening, no solder paste"
  rect 10x10 smd paste-5 mask-5: 1(-10,0) 2(10,0)
QFN4.5X3.5MM_8PWD [mm]
  rect 0.2x0.7 smd mask+0.03: 1(-1.55,-1.7) 2(-1.15,-1.7) 3(-0.75,-1.7) 6(-0.75,1.7) 7(-1.15,1.7) 8(-1.55,1.7)
  rect 2.1x0.7 smd mask+0.03: 4(0.6,-1.7) 5(0.6,1.7)
  rect 3.95x2.1 smd: 9(0,0)
QFN48[RGZ] [mil]
  rrect50% 35x12 smd mask+2: 1(-137.5,108.3) 2(-137.5,88.6) 3(-137.5,68.9) 4(-137.5,49.2) 5(-137.5,29.5) 6(-137.5,9.8) 7(-137.5,-9.9) 8(-137.5,-29.6) 9(-137.5,-49.3) 10(-137.5,-69) 11(-137.5,-88.7) 12(-137.5,-108.4) 25(137.5,-108.4) 26(137.5,-88.7) 27(137.5,-69) 28(137.5,-49.3) 29(137.5,-29.6) 30(137.5,-9.9) 31(137.5,9.8) 32(137.5,29.5) 33(137.5,49.2) 34(137.5,68.9) 35(137.5,88.6) 36(137.5,108.3)
  rrect50% 12x35 smd mask+2: 13(-108.4,-137.6) 14(-88.7,-137.6) 15(-69,-137.6) 16(-49.3,-137.6) 17(-29.6,-137.6) 18(-9.9,-137.6) 19(9.8,-137.6) 20(29.5,-137.6) 21(49.2,-137.6) 22(68.9,-137.6) 23(88.6,-137.6) 24(108.3,-137.6) 37(108.3,137.4) 38(88.6,137.4) 39(68.9,137.4) 40(49.2,137.4) 41(29.5,137.4) 42(9.8,137.4) 43(-9.9,137.4) 44(-29.6,137.4) 45(-49.3,137.4) 46(-69,137.4) 47(-88.7,137.4) 48(-108.4,137.4)
  rect 200x200 smd: 49(0,0)
"QI Logo" [mil]
  silkscreen extent -133,-60 71,230
R603 [mil]
  rect 30x40 smd: 1(-35,0) 2(35,0)
R0603 [mil]
  rect 30x40 smd: 1(-35,0) 2(35,0)
R0805 [mil]
  rect 40x60 smd: 1(-40,0) 2(40,0)
SNT-100-BK-G [mil] "Samtec STEP model"
  round 1 on Mech3: 0(0,0)
SOT-23 [mil]
  rect 29.5x25 smd mask+2.5: 1(40.25,-37.4) 2(40.25,37.4) 3(-40.25,0)
SOT-323#1 [mil]
  rect 20x30 smd: 1(-25,-35) 2(25,-35) 3(0,35)
SOT-323#2 [mil]
  rect 20x30 smd: 1(25,-35) 2(-25,-35) 3(0,35)
TH-63 [mil]
  rect 100x100 hole 63: 1(0,0)
TI_Horizontal_Overlay_Medium [mil]
TP_40_SMT [mil]
  round 40 smd: 1(0,0)
TP_1045 [mil]
  round 70 hole 43: 1(0,0)

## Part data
1A1: "Single point connection between nets."
C1 C3 C20 C34: "Capacitor, Ceramic, 1UF 16V 10% X7R 0603"
C2 C17: "CAP, CERM, 4.7uF, 10V, +/-10%, X5R, 0805"
C4: "Capacitor, Ceramic, 4700PF 50V 5% NP0 0603"
C5: "Capacitor, Ceramic, 4.7uF, 10V, X7R, 20%"
C6 C15 C16 C31: "Capacitor, Ceramic, 0.1UF 50V 10% X7R 0603"
C7: "Capacitor, Ceramic, 22UF 25V 10% X5R 1210"
C8: "Capacitor, Ceramic, 2.2UF 10V 10% X7R 0603"
C9 C13: "CAP, CERM, 1uF, 16V, +/-10%, X5R, 0603"
C10: "Capacitor, Ceramic, 50V, C0G, 5%"
C11 C25: "Capacitor, Ceramic, 4.7UF 10V 20% X5R 0603"
C12: "Capacitor, Ceramic Chip, 2.2UF 16V 10% X7R 1206"
C14: "Capacitor, Ceramic, 33PF 50V 5% NP0 0603"
C18: "Capacitor, Ceramic, 4700pF, 50V, X7R, 10%"
C19 C26: "Capacitor, Ceramic,  4.7UF 10V 20% X5R 0603"
C21: "Capacitor, Ceramic, 0.01uF, 50V, X7R, 10%"
C22: "Capacitor, Ceramic,  4.7UF 10V 20% X5R 060"
C23 C33: "CAP, CERM, 10uF, 10V, +/-10%, X5R, 1210"
C24: "Capacitor, Ceramic, 4.7uF, 50V, X7R, 10%"
C27 C28 C29: "CAP, CERM, 0.1uF, 100V, +10/%, X7R, 1206"
C30: library part VJ1210Y104KBBAT4X, "CAP CER 0.1UF 50V 10% NP0 1210"
C32: "Capacitor, Ceramic Chip, 100UF 6.3V 20% X5R 1206"
D1: "Diode. LED 2X1.2MM 470NM BL WTR CLR SMD"
D2 D3 D8: "Diode, Schottky, 200-mA, 30-V"
D4: "Diode, Dual Schottky, 200mA, 30V"
D5: "Diode. LED 2X1.2MM 568NM GN WTR CLR SMD"
D7: "Diode. LED 2X1.2MM 640NM RD WTR CLR SMD"
D9: "Diode. LED 2X1.2MM 601NM OR WTR CLR SMD"
FID1 FID2 FID3: "Fiducial mark.  There is nothing to buy or mount."
J1 J2 JP1 JP2 JP3: "Header, Male 2-pin, 100mil spacing,"
J3: "Header, 2x7 pin, 100mil spacing, Straight, 4 Wall"
J4: "Connector, Male Straight 2x5 pin, 100mil spacing, 4 Wall"
J5: "Connector, SMT, Micro USB-B"
L1 L3: "Inductor, Toroid, yyA, zzmilliohm"
L2: "TX Coil"
Logo2: library part TI_Logo, "Texas Instrument Corporate Signature"
Logo3: library part "Qi PCB Logo"
Q4 Q7: library part TR-BSS138, "MOSFET, Nch, 50V, 0.22A, 3.5 Ohm"
Q8: library part TR-DTC114EUA, "Transistor, Digital NPN, 50 V, 100 mA"
R1 R3 R37: "Resistor, Chip, 1.0 OHM 1/10W 5% 0603 SMD"
R2 R47: "Resistor, Chip, 10 OHM 1/10W 5% 0603 SMD"
R4 R46 R55: "Resistor, Chip, 1.00K OHM 1/10W 1% 0603 SMD"
R5 R8 R9 R11 R18 R19 R40 R41 R43 R52: "RES 10.0K OHM 1/10W 1% 0603 SMD"
R6: "Resistor, Chip, 100K OHM 1/10W 1% 0603 SMD"
R7: "Resistor, Chip, 22 OHM 1/8W 5% 0805 SMD"
R10: "Resistor, Chip, 76.8K OHM 1/10W 1% 0603 SMD"
R12 R21 R24 R31 R35 R38 R39 R42 R49: "Resistor, Chip, 1/16W, 1%"
R14: "Resistor, Chip,  12.1K OHM 1/10W 1% 0603 SMD"
R15 R16 R33: "Resistor, Chip, 475 OHM 1/10W 1% 0603 SMD"
R17: "Resistor, Chip,  3.60K OHM 1/10W 1% 0603 SMD"
R22: "Resistor, Chip,  56.2K OHM 1/10W 1% 0603 SMD"
R23: "Resistor, Chip, 56.2K OHM 1/10W 1% 0603 SMD"
R25 R28 R30 R54: "Resistor, Chip, 523K OHM 1/10W 1% 0603 SMD"
R26 R29: "Resistor, Chip,  10 OHM 1/10W 5% 0603 SMD"
R27: "Resistor, Chip, 56.2K OHM 1/10W 1%"
R32: "Resistor, Chip, 0.02 OHM 1/2W 1% 0805 SMD"
R36: "Resistor, Chip,  1.0 OHM 1/10W 5% 0603 SMD"
R45: "RES, 1.0Meg ohm, 5%, 0.1W, 0603"
R48: "Resistor, Chip, 3.60K OHM 1/10W 1% 0603 SMD"
R50: "Resistor, Chip,  475 OHM 1/10W 1% 0603 SMD"
R51: "Resistor, Chip, 1.00M OHM 1/10W 1% 0603 SMD"
R53: "Resistor, Chip,  2.00M OHM 1/10W 1% 0603 SMD"
R99: "RES, 86.6k ohm, 1%, 0.1W, 0603"
SH-J1: "Shunt, 100mil, Gold plated, Black"
TP1: "Test Point, White, Thru Hole"
TP2 TP3 TP13 TP19: "Post, Wirewrap, 0.043 press-fit, For 0.015-0.025 pins"
TP4: "Test Point, Black, Thru Hole"
TP9 TP10 TP14 TP18 TP20 TP25 TP26 TP27 TP28: "Test point, 40 mil SMT"
U1: "IC, Qi Compliant Wireless Power Transmitter Manager"
U2 U3: "IC, Synchronous Buck NexFETPower Stage"
U5: library part TLV713XXDBV, "IC REG LDO 3.3V 200mA SOT-23-5"
U7: "IC,  Current Monitor, High or Low Side Measurement,  Bi-Directional Zerø-Drift Series"
ZZ1: library part AssemblyNoteLabel
ZZ2 ZZ3 ZZ4 ZZ5 ZZ6 ZZ7 ZZ8 ZZ9 ZZ10: library part AssemblyNote

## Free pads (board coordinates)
  round 60 hole 125 unplated: 0(410,112) 0(410,2738) 0(4790,112) 0(4790,2738)
  round 150 hole 125 unplated: 0(2600,200) 0(2600,2650) 0(5050,200) 0(5050,2650)

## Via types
v1: diameter 25, hole 15, Top Layer to Bottom Layer, tented both sides, 50 vias
v2: diameter 20, hole 10, Top Layer to Bottom Layer, tented both sides, 47 vias
v3: diameter 26, hole 10, Top Layer to Bottom Layer, tented both sides, 34 vias
v4: diameter 23.62, hole 11.81, Top Layer to Bottom Layer, tented bottom, 25 vias

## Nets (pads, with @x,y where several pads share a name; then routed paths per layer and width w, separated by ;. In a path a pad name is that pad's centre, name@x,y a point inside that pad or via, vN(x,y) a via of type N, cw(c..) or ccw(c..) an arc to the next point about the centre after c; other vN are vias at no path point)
3V3_ADC: C3.2 C5.1 R7.2 TP10.1 U1.34 | length 409
  Top Layer w8: C3.2@1615,830 1630,815 1675,815 1726.1,866.1 U1.34@1777.5,866.1
  Top Layer w20: TP10.1@1465,755 1465,820 1475,830 C5.1@1545,830 C3.2@1615,830
3V3_VCC: C1.2 C8.1 C19.1 C21.2 C25.2 R7.1 R9.2 R14.2 R19.2 R21.1 R31.1 R35.1 R38.1 R39.1 R40.1 R41.1 R42.1 R49.1 TP9.1 U1.33 U5.5 U7.3 | length 4917.1
  Top Layer w8: C8.1@1545,610 1545,530 R41.1@1550,525 R40.1@1615,525 v2(1670,525) ; C8.1@1545,615 1555,615 1580,590 v2(1580,575) ; C1.2@1615,890 1650,855 1685,855 1714,884 1775.7,884 U1.33@1777.5,885.8
  Top Layer w10: v1(395,1165) R19.2@395,1215 ; C25.2@1370,775 1362,775 U5.5@1362,860.5 1362,865 1397,900 R7.1@1465,900 ; R7.1@1469,890 R7.1@1475,890 ; v2(1506,942) 1493,942 TP9.1@1465,970 ; C19.1@1545,890 R7.1@1475,890 ; C19.1@1551.5,896.5 1558,890 C1.2@1615,890 ; U7.3@1666.1,1286.6 1666.1,1217 1675,1217 C21.2@1675,1210 1605,1140 1544.58,1140 1500,1095.42 1500,1035 1465,1000 TP9.1@1465,970 ; v3(1915,430) 1957,430 1975,448 R14.2@1975,480 ; R9.2@2245,890 2245,897 2265,917 2265,937 2306,978 v2(2306,1017) ; R7.1@1465,900 TP9.1@1465,970 ; R7.1@1465,900 R7.1@1475,890
  INTERNAL 2 w10: v2(1506,942) 1532,942 1664,1074 2285,1074 2306,1053 v2(2306,1017)
  Bottom Layer w8: v2(1580,575) 1580,790 1645,855 v1(1655,855) ; v2(1670,525) 1680,515 R42.1@1680,430
  Bottom Layer w10: v1(395,1165) 395,945 420,920 1445,920 1467,942 v2(1506,942) ; R42.1@1667,430 1680,430 R39.1@1757,430 R49.1@1860,430 v3(1915,430) R38.1@1957,430 R35.1@2057,430 R31.1@2157,430 R21.1@2217,430
/TRST: J3.2 R43.2 U1.31 | length 1188.9
  Top Layer w8: R43.2@1620,1075 1661.5,1033.5 1661.5,918.5 1675,905 1739,905 1759,925 U1.31@1777.3,925
  Top Layer w10: U1.31@1777.3,925 U1.31@1777.5,925.2
  Bottom Layer w10: J3.2@1612,264 1610,285 1612.33,264.04 1612.5,262.5 1612.5,264 1453,423.5 1453,552 1514.99,613.99 1514.99,819.99 1605,910 v2(1670,910)
AGND: 1A1.2 C1.1 C2.2 C3.1 C4.2 C5.2 C10.1 C11.2 C12.1 C14.1 C16.1 C19.2 C20.2 C21.1 C22.1 C24.2 C25.1 C26.1 C32.2 D1.1 D5.1 D7.1 D9.1 J3.4 J3.8 J3.10 J3.12 J4.6 JP1.2 JP2.1 JP3.2 L3.3 Q4.2 Q7.2 R5.1 R8.1 R11.1 R17.1 R18.1 R23.1 R26.2 R28.1 R43.1 R48.1 R51.1 R52.1 TP4.1 U1.20 U1.32 U1.36 U1.47 U1.48 U1.49 U5.2 U7.1 U7.2 | length 5732
  Top Layer w8: U1.36@1777.5,826.7 1777.9,827.1 1807.17,827.1 U1.49@1836.26,856.19 ; U1.49@1885.5,1023.61 U1.20@1885.5,1072.6
  Top Layer w10: JP3.2@206,1919 JP3.2@206,1930.69 ; 1A1.2@1180,2165 C2.2@1180,2230 ; U1.32@1777.5,905.5 U1.49@1885.5,905.5 ; 2685,385 v3(3050,385) v3(3470,385)
  Top Layer w20: 2685,385 v3(2685,650) v3(2685,865) v3(2685,1130) v3(2685,1345) v3(2685,1560) v3(2685,1825) v3(2685,2040) v3(2685,2255) v3(2685,2425)
  INTERNAL 2 w10: v3(2685,2040) v3(2685,2255) v3(2685,2425)
  Bottom Layer w10: v1(1200,755) v2(1259,755) ; v2(1221,2354) 1282,2415 v3(3045,2415) ; 2685,385 v3(2685,650) 2685,694.09
  other v1: 2510,110 2505,295 2505,470 2155,480 2150,550 2155,620 2505,650 1320,710 1670,755 2140,780 2505,865 1550,1020 2505,1130 2495,1345 2505,1560 2515,1825 2505,2060 1085,2190 1085,2225 1085,2265
  other v2: 1665,615
  other v3: 3825,385 4175,385 4595,385 5025,385 5025,650 5025,870 5025,1130 5025,1345 5025,1565 5020,1825 5020,2045 5020,2260 3470,2425 3820,2425 4175,2425 4590,2425 5020,2425
  other v4: 1836.26,856.26 1875.63,856.26 1915,856.26 1954.37,856.26 1993.74,856.26 1836.26,895.63 1875.63,895.63 1915,895.63 1954.37,895.63 1993.74,895.63 1836.26,935 1875.63,935 1915,935 1954.37,935 1993.74,935 1836.26,974.37 1875.63,974.37 1915,974.37 1954.37,974.37 1993.74,974.37 1836.26,1013.74 1875.63,1013.74 1915,1013.74 1954.37,1013.74 1993.74,1013.74
CLK: J4.9 R40.2 U1.10 | length 2843.7
  Top Layer w8: U1.10@2052.5,1004 2229,1004 v2(2240,1015)
  Top Layer w10: J4.9@1172.5,162.5 1322.5,162.5 R40.2@1615,455
  Bottom Layer w10: J4.9@1172.5,162.5 1457.5,162.5 1549,71 1858.37,71 1902.37,115 2257,115 2271,129 2271,899 2289,917 2289,991 2265,1015 2243,1015 v2@2241.5,1013.5
COMM+: R12.1 R29.2 TP13.1 U1.37 U1.39 | length 1095.5
  Top Layer w8: R29.2@1846.1,691.1 U1.39@1846.1,797.6 ; TP13.1@1930,670 2007.87,592.13 2007.87,457.13 2025,440 2060,440 2080,460 2080,570 2095,585 2155,585 R12.1@2190,550
  Top Layer w10: U1.37@1806.7,797.6 1806.7,778.7 1730,702 1730,660 1740,650 1800,650 1831.95,681.95 1843.05,681.95 R29.2@1846.1,685 ; R29.2@1840,685 R29.2@1843,685 ; TP13.1@1930,670 1915,685 R29.2@1846.1,685 ; R29.2@1843,685 R29.2@1846.1,685 ; R29.2@1843,685 1843,691.1 1846.1,691.1 R29.2@1846.1,685
COMM-: R26.1 U1.38 U1.40 | length 286.7
  Top Layer w8: R26.1@1770,685 1804,719 v2(1822,719) 1826.4,723.4 U1.38@1826.4,797.6
  Top Layer w10: v2(1822,719) v2@1826.4,723.4 ; U1.40@1865.8,797.6 1865.8,727.2 v2(1874,719)
  INTERNAL 2 w10: v2(1822,719) v2(1874,719)
DATA: J4.10 R41.2 U1.11 | length 3065.4
  Top Layer w10: J4.10@1172.5,262.5 1357.5,262.5 R41.2@1550,455 ; U1.11@2052.5,1023.7 2214.76,1023.7 v2@2241.06,1050
  Bottom Layer w10: J4.10@1172.5,262.5 1123,213 1123,123 1198,48 1877,48 1923,94 2268.63,94 2293,118.37 2293,890 2313,910 2313,990.06 2330,1007.06 2330,1026.94 2315.94,1041 2254,1041 v2(2245,1050)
